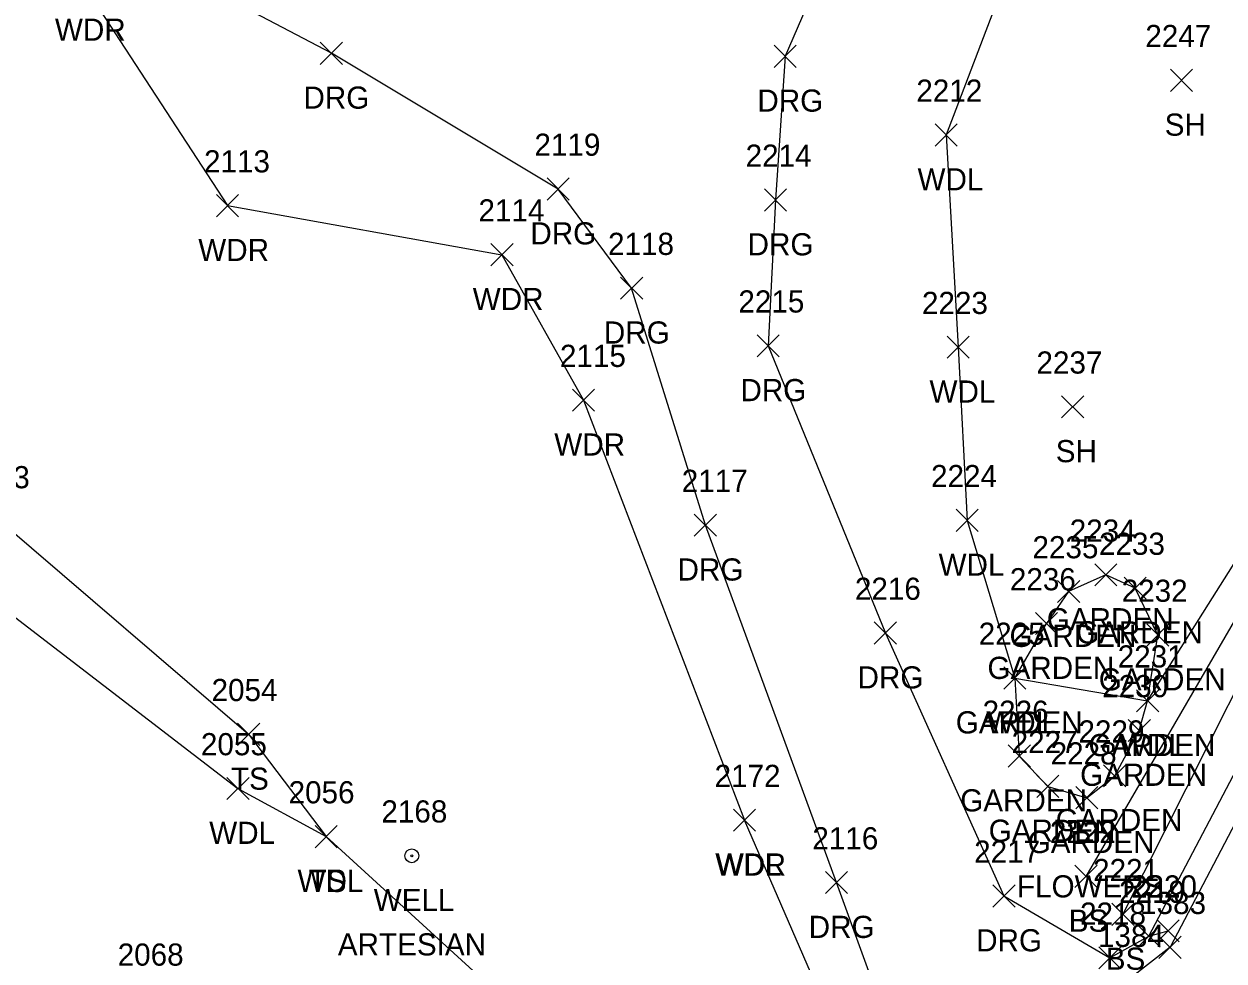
# Model space of a CAD drawing. Extents: x 1885914 to 1887218, y 756253 to 760620.
# Drawn here: x 1886470.3 to 1886578.6, y 760110.4 to 760195 of the extents above; entities that cross this region are included whole.
import ezdxf

# ---------------------------------------------------------------- set-up
doc = ezdxf.new("R2010")
doc.units = 0
for name, color, linetype in [('L_A', 7, 'Continuous'), ('L_C', 7, 'Continuous'), ('L_I', 7, 'Continuous'), ('L_TIC', 7, 'Continuous'), ('LAPB', 7, 'Continuous'), ('LAWA', 7, 'Continuous'), ('LELB', 7, 'Continuous'), ('P_I', 7, 'Continuous'), ('P_TIC', 7, 'Continuous'), ('PET', 7, 'Continuous'), ('R_A', 7, 'Continuous'), ('R_I', 7, 'Continuous'), ('R_TIC', 7, 'Continuous'), ('RDG', 7, 'Continuous'), ('U_A', 7, 'Continuous'), ('U_C', 7, 'Continuous'), ('U_I', 7, 'Continuous'), ('UWW', 7, 'Continuous')]:
    doc.layers.add(name, color=color, linetype=linetype)

msp = doc.modelspace()

# ---------------------------------------------------------------- linework, layer by layer
at = {"layer": 'L_TIC'}
for points in [[(1886573.76, 760188.88), (1886575.76, 760190.88)], [(1886575.76, 760188.88), (1886573.76, 760190.88)], [(1886552.53, 760183.95), (1886554.53, 760185.95)], [(1886554.53, 760183.95), (1886552.53, 760185.95)], [(1886487.7, 760177.57), (1886489.7, 760179.57)], [(1886489.7, 760177.57), (1886487.7, 760179.57)], [(1886512.46, 760173.14), (1886514.46, 760175.14)], [(1886514.46, 760173.14), (1886512.46, 760175.14)], [(1886553.61, 760164.79), (1886555.61, 760166.79)], [(1886555.61, 760164.79), (1886553.61, 760166.79)], [(1886519.82, 760160.01), (1886521.82, 760162.01)], [(1886521.82, 760160.01), (1886519.82, 760162.01)], [(1886563.94, 760159.41), (1886565.94, 760161.41)], [(1886565.94, 760159.41), (1886563.94, 760161.41)], [(1886554.43, 760149.16), (1886556.43, 760151.16)], [(1886556.43, 760149.16), (1886554.43, 760151.16)], [(1886566.94, 760144.24), (1886568.94, 760146.24)], [(1886568.94, 760144.24), (1886566.94, 760146.24)], [(1886563.58, 760142.74), (1886565.58, 760144.74)], [(1886565.58, 760142.74), (1886563.58, 760144.74)], [(1886569.58, 760143.05), (1886571.58, 760145.05)], [(1886571.58, 760143.05), (1886569.58, 760145.05)], [(1886561.59, 760139.85), (1886563.59, 760141.85)], [(1886563.59, 760139.85), (1886561.59, 760141.85)], [(1886561.59, 760139.85), (1886563.59, 760141.85)], [(1886563.59, 760139.85), (1886561.59, 760141.85)], [(1886571.63, 760138.81), (1886573.63, 760140.81)], [(1886573.63, 760138.81), (1886571.63, 760140.81)], [(1886558.73, 760134.93), (1886560.73, 760136.93)], [(1886560.73, 760134.93), (1886558.73, 760136.93)], [(1886558.73, 760134.93), (1886560.73, 760136.93)], [(1886560.73, 760134.93), (1886558.73, 760136.93)], [(1886558.73, 760134.93), (1886560.73, 760136.93)], [(1886560.73, 760134.93), (1886558.73, 760136.93)], [(1886570.71, 760132.88), (1886572.71, 760134.88)], [(1886572.71, 760132.88), (1886570.71, 760134.88)], [(1886570.71, 760132.88), (1886572.71, 760134.88)], [(1886572.71, 760132.88), (1886570.71, 760134.88)], [(1886489.6, 760129.85), (1886491.6, 760131.85)], [(1886491.6, 760129.85), (1886489.6, 760131.85)], [(1886569.96, 760130.2), (1886571.96, 760132.2)], [(1886571.96, 760130.2), (1886569.96, 760132.2)], [(1886559.13, 760127.89), (1886561.13, 760129.89)], [(1886561.13, 760127.89), (1886559.13, 760129.89)], [(1886567.74, 760126.11), (1886569.74, 760128.11)], [(1886569.74, 760126.11), (1886567.74, 760128.11)], [(1886488.64, 760124.96), (1886490.64, 760126.96)], [(1886490.64, 760124.96), (1886488.64, 760126.96)], [(1886561.7, 760125.15), (1886563.7, 760127.15)], [(1886563.7, 760125.15), (1886561.7, 760127.15)], [(1886565.22, 760124.13), (1886567.22, 760126.13)], [(1886567.22, 760124.13), (1886565.22, 760126.13)], [(1886534.34, 760122.1), (1886536.34, 760124.1)], [(1886536.34, 760122.1), (1886534.34, 760124.1)], [(1886534.34, 760122.1), (1886536.34, 760124.1)], [(1886536.34, 760122.1), (1886534.34, 760124.1)], [(1886496.6, 760120.62), (1886498.6, 760122.62)], [(1886498.6, 760120.62), (1886496.6, 760122.62)], [(1886496.6, 760120.62), (1886498.6, 760122.62)], [(1886498.6, 760120.62), (1886496.6, 760122.62)], [(1886565.15, 760117.03), (1886567.15, 760119.03)], [(1886567.15, 760117.03), (1886565.15, 760119.03)], [(1886568.48, 760113.6), (1886570.48, 760115.6)], [(1886570.48, 760113.6), (1886568.48, 760115.6)], [(1886570.83, 760111.64), (1886572.83, 760113.64)], [(1886572.83, 760111.64), (1886570.83, 760113.64)]]:
    msp.add_lwpolyline(points, dxfattribs=at)
at = {"layer": 'LAPB'}
for points in [[(1886559.73, 760135.93), (1886560.13, 760128.89), (1886562.7, 760126.15), (1886566.22, 760125.13), (1886568.74, 760127.11), (1886570.96, 760131.2), (1886571.71, 760133.88), (1886572.63, 760139.81), (1886570.58, 760144.05), (1886567.94, 760145.24), (1886564.58, 760143.74), (1886562.59, 760140.85)], [(1886559.73, 760135.93), (1886562.59, 760140.85)]]:
    msp.add_lwpolyline(points, dxfattribs=at)
at = {"layer": 'LAWA'}
for points in [[(1886557.49, 760303.87), (1886591.46, 760287.38), (1886586.6, 760261.32), (1886572.4, 760231.51), (1886560.84, 760204.17), (1886553.53, 760184.95), (1886554.61, 760165.79), (1886555.43, 760150.16), (1886559.73, 760135.93), (1886571.71, 760133.88), (1886584.52, 760154.18), (1886595.31, 760177.7), (1886612.55, 760208.5), (1886627.73, 760237.63), (1886641.55, 760264.82), (1886659.69, 760306.49), (1886641.28, 760308.88), (1886618.53, 760315.27), (1886578.46, 760329), (1886533.46, 760348.84), (1886508.34, 760359)], [(1886416.83, 760225.49), (1886440.02, 760212.45), (1886451.63, 760212.99), (1886475.76, 760198.45), (1886488.7, 760178.57), (1886513.46, 760174.14), (1886520.82, 760161.01), (1886535.34, 760123.1)], [(1886410.21, 760202.66), (1886433.18, 760175.41), (1886448.67, 760158.75), (1886465.42, 760144.55), (1886489.64, 760125.96), (1886497.6, 760121.62), (1886524.44, 760097.09), (1886536.37, 760086.88), (1886546.94, 760096.36), (1886535.34, 760123.1)]]:
    msp.add_lwpolyline(points, dxfattribs=at)
at = {"layer": 'LELB'}
for points in [[(1886566.15, 760118.03), (1886586.71, 760153.39), (1886597.76, 760175.93), (1886614.93, 760207.48), (1886633.43, 760234.81), (1886648.4, 760263.02), (1886665.33, 760301.86), (1886680.82, 760329.69), (1886690.65, 760354.87)], [(1886569.48, 760114.6), (1886588.52, 760152.37), (1886601.13, 760173.25), (1886619.2, 760206.04), (1886634.53, 760234.24), (1886649.4, 760262.46), (1886668.06, 760300.13), (1886683.15, 760328.96), (1886694.25, 760353.25)], [(1886571.83, 760112.64), (1886591.92, 760150.85), (1886603.31, 760171.7), (1886621.88, 760204.85), (1886636.21, 760233.06), (1886650.97, 760261.46), (1886669.74, 760299.13), (1886684.78, 760328.15), (1886696.37, 760352.36)], [(1886448.67, 760158.75), (1886468.25, 760150.06), (1886490.6, 760130.85), (1886497.6, 760121.62)]]:
    msp.add_lwpolyline(points, dxfattribs=at)
at = {"layer": 'P_TIC'}
for points in [[(1886572.73, 760110.63), (1886574.73, 760112.63)], [(1886574.73, 760110.63), (1886572.73, 760112.63)]]:
    msp.add_lwpolyline(points, dxfattribs=at)
at = {"layer": 'PET'}
msp.add_lwpolyline([(1886697.38, 760351.34), (1886683.55, 760324.32), (1886670.92, 760299), (1886655.54, 760267.57), (1886637.84, 760233.45), (1886621.76, 760202.26), (1886604.96, 760170.92), (1886588.13, 760139.08), (1886573.73, 760111.63), (1886569.92, 760108.66), (1886558.78, 760086.23), (1886539.06, 760048.09), (1886538, 760043.12), (1886529.58, 760026.84), (1886519.95, 760007.47), (1886505.21, 759975.04), (1886485.32, 759931.76)], dxfattribs=at)
at = {"layer": 'R_TIC'}
for points in [[(1886497.07, 760191.32), (1886499.07, 760193.32)], [(1886499.07, 760191.32), (1886497.07, 760193.32)], [(1886538.01, 760191.05), (1886540.01, 760193.05)], [(1886540.01, 760191.05), (1886538.01, 760193.05)], [(1886517.53, 760179.07), (1886519.53, 760181.07)], [(1886519.53, 760179.07), (1886517.53, 760181.07)], [(1886537.13, 760178.08), (1886539.13, 760180.08)], [(1886539.13, 760178.08), (1886537.13, 760180.08)], [(1886524.16, 760170.12), (1886526.16, 760172.12)], [(1886526.16, 760170.12), (1886524.16, 760172.12)], [(1886536.48, 760164.92), (1886538.48, 760166.92)], [(1886538.48, 760164.92), (1886536.48, 760166.92)], [(1886530.81, 760148.73), (1886532.81, 760150.73)], [(1886532.81, 760148.73), (1886530.81, 760150.73)], [(1886547.05, 760138.99), (1886549.05, 760140.99)], [(1886549.05, 760138.99), (1886547.05, 760140.99)], [(1886542.64, 760116.47), (1886544.64, 760118.47)], [(1886544.64, 760116.47), (1886542.64, 760118.47)], [(1886557.75, 760115.26), (1886559.75, 760117.26)], [(1886559.75, 760115.26), (1886557.75, 760117.26)], [(1886570.83, 760111.64), (1886572.83, 760113.64)], [(1886572.83, 760111.64), (1886570.83, 760113.64)], [(1886572.56, 760112.12), (1886574.56, 760114.12)], [(1886574.56, 760112.12), (1886572.56, 760114.12)], [(1886567.3, 760109.67), (1886569.3, 760111.67)], [(1886569.3, 760109.67), (1886567.3, 760111.67)]]:
    msp.add_lwpolyline(points, dxfattribs=at)
at = {"layer": 'RDG'}
for points in [[(1886545.75, 760291.46), (1886562.57, 760278.75), (1886574.43, 760271.84), (1886560.81, 760237.29), (1886547.52, 760211.75), (1886539.01, 760192.05), (1886538.13, 760179.08), (1886537.48, 760165.92), (1886548.05, 760139.99), (1886558.75, 760116.26), (1886568.3, 760110.67), (1886571.83, 760112.64), (1886573.56, 760113.12)], [(1886454.48, 760119.53), (1886487.38, 760097.68), (1886513.73, 760081.78), (1886534.81, 760073.6), (1886543.18, 760075.46), (1886550.17, 760080.85), (1886553.86, 760089.33), (1886543.64, 760117.47), (1886531.81, 760149.73), (1886525.16, 760171.12), (1886518.53, 760180.07), (1886498.07, 760192.32), (1886477.19, 760203.32), (1886461.39, 760213.36)]]:
    msp.add_lwpolyline(points, dxfattribs=at)
at = {"layer": 'UWW'}
for radius in [0.625, 0.0833]:
    msp.add_circle((1886505.32, 760119.89), radius, dxfattribs=at)

# ---------------------------------------------------------------- texts
at = {"layer": 'L_A'}
for s, p in [('WDR', (1886473.13, 760193.45)), ('SH', (1886573.25, 760184.88)), ('WDL', (1886550.95, 760179.95)), ('WDR', (1886486.06, 760173.57)), ('WDR', (1886510.82, 760169.14)), ('WDL', (1886552.03, 760160.79)), ('WDR', (1886518.18, 760156.01)), ('SH', (1886563.42, 760155.41)), ('WDL', (1886552.85, 760145.16)), ('GARDEN', (1886562.61, 760140.24)), ('GARDEN', (1886559.25, 760138.74)), ('GARDEN', (1886565.25, 760139.05)), ('GARDEN', (1886557.26, 760135.85)), ('GARDEN', (1886557.26, 760135.85)), ('GARDEN', (1886567.3, 760134.81)), ('GARDEN', (1886554.4, 760130.93)), ('GARDEN', (1886554.4, 760130.93)), ('WDL', (1886557.15, 760130.93)), ('GARDEN', (1886566.38, 760128.88)), ('WDL', (1886569.12, 760128.88)), ('TS', (1886489.01, 760125.85)), ('GARDEN', (1886565.62, 760126.2)), ('GARDEN', (1886554.8, 760123.89)), ('GARDEN', (1886563.41, 760122.11)), ('WDL', (1886487.05, 760120.96)), ('GARDEN', (1886557.37, 760121.15)), ('GARDEN', (1886560.89, 760120.13)), ('WDR', (1886532.7, 760118.1)), ('WDL', (1886532.76, 760118.1)), ('WDL', (1886495.02, 760116.62)), ('TS', (1886496.01, 760116.62)), ('BS', (1886564.59, 760113.03)), ('BS', (1886567.93, 760109.6))]:
    msp.add_text(s, height=2, dxfattribs=at).set_placement(p)
at = {"layer": 'L_C'}
msp.add_text('FLOWERS', height=2, dxfattribs=at).set_placement((1886559.92, 760116.13))
at = {"layer": 'L_I'}
for s, p in [('2247', (1886571.5, 760192.88)), ('2212', (1886550.84, 760187.95)), ('2113', (1886486.58, 760181.57)), ('2114', (1886511.34, 760177.14)), ('2223', (1886551.35, 760168.79)), ('2115', (1886518.69, 760164.01)), ('2237', (1886561.68, 760163.41)), ('2053', (1886464.91, 760153.06)), ('2224', (1886552.17, 760153.16)), ('2234', (1886564.68, 760148.24)), ('2233', (1886567.32, 760147.05)), ('2235', (1886561.32, 760146.74)), ('2236', (1886559.28, 760143.85)), ('2236', (1886559.28, 760143.85)), ('2232', (1886569.37, 760142.81)), ('2225', (1886556.47, 760138.93)), ('2225', (1886556.47, 760138.93)), ('2225', (1886556.47, 760138.93)), ('2231', (1886569.01, 760136.88)), ('2231', (1886569.01, 760136.88)), ('2230', (1886567.61, 760134.2)), ('2054', (1886487.26, 760133.85)), ('2226', (1886556.82, 760131.89)), ('2229', (1886565.47, 760130.11)), ('2055', (1886486.3, 760128.96)), ('2227', (1886559.44, 760129.15)), ('2228', (1886562.96, 760128.13)), ('2172', (1886532.64, 760126.1)), ('2172', (1886532.64, 760126.1)), ('2056', (1886494.21, 760124.62)), ('2056', (1886494.21, 760124.62)), ('2222', (1886562.89, 760121.03)), ('2221', (1886566.79, 760117.6)), ('2219', (1886569.13, 760115.64)), ('2068', (1886478.79, 760109.97))]:
    msp.add_text(s, height=2, dxfattribs=at).set_placement(p)
at = {"layer": 'P_I'}
for s, p in [('1383', (1886571.03, 760114.63)), ('1384', (1886567.23, 760111.66))]:
    msp.add_text(s, height=2, dxfattribs=at).set_placement(p)
at = {"layer": 'R_A'}
for p in [(1886495.55, 760187.32), (1886536.5, 760187.05), (1886516.02, 760175.07), (1886535.62, 760174.08), (1886522.65, 760166.12), (1886534.97, 760160.92), (1886529.3, 760144.73), (1886545.54, 760134.99), (1886541.13, 760112.47), (1886556.24, 760111.26)]:
    msp.add_text('DRG', height=2, dxfattribs=at).set_placement(p)
at = {"layer": 'R_I'}
for s, p in [('2119', (1886516.39, 760183.07)), ('2214', (1886535.44, 760182.08)), ('2118', (1886523.03, 760174.12)), ('2215', (1886534.79, 760168.92)), ('2117', (1886529.68, 760152.73)), ('2216', (1886545.3, 760142.99)), ('2116', (1886541.46, 760120.47)), ('2217', (1886556.06, 760119.26)), ('2219', (1886569.13, 760115.64)), ('2220', (1886570.21, 760116.12)), ('2218', (1886565.61, 760113.67))]:
    msp.add_text(s, height=2, dxfattribs=at).set_placement(p)
at = {"layer": 'U_A'}
msp.add_text('WELL', height=2, dxfattribs=at).set_placement((1886501.89, 760114.89))
at = {"layer": 'U_C'}
msp.add_text('ARTESIAN', height=2, dxfattribs=at).set_placement((1886498.65, 760110.89))
at = {"layer": 'U_I'}
msp.add_text('2168', height=2, dxfattribs=at).set_placement((1886502.58, 760122.89))

doc.saveas('drawing.dxf')
